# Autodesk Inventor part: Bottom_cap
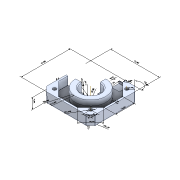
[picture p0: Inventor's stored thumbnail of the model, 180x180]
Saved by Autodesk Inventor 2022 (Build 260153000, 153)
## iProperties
Created: 2020-10
Part Number: Bottom_cap
Material: Generico
Document SubType Name: Modeling
Designer: admin
Density: 1 g/cm^3
Appearance: Default
Sending System: SolidWorks 2020
Last Author: Simon
Last Saved: 2020-10-31
Author: admin
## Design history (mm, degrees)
node "Annotazioni"
  node "Quota lineare 2" dims "d5" = 42 (derived), "d80" = 9.49768 (derived)
  node "Quota lineare 3" dims "d8" = 42 (derived), "d80" = 9.49768 (derived)
  node "Quota lineare 4" dims "d11" = 16.07149 (derived), "d80" = 9.49768 (derived)
  node "Quota lineare 5" dims "d14" = 16.07149 (derived), "d80" = 9.49768 (derived)
  node "Quota radiale 1" dims "d16" = 13 (derived), "d80" = 9.49768 (derived)
  node "Quota radiale 2" dims "d18" = 8 (derived), "d80" = 9.49768 (derived)
  node "Quota lineare 6" dims "d21" = 5.5 (derived), "d80" = 9.49768 (derived)
  node "Quota lineare 7" dims "d24" = 5.5 (derived), "d80" = 9.49768 (derived)
  node "Quota diametro 1" dims "d26" = 3 (derived), "d80" = 9.49768 (derived)
  node "Quota lineare 8" dims "d29" = 1.5 (derived), "d80" = 9.49768 (derived)
  node "Quota lineare 10" dims "d35" = 9 (derived), "d80" = 9.49768 (derived)
  node "Quota lineare 11" dims "d38" = 2 (derived), "d80" = 9.49768 (derived)
  node "Quota diametro 2" dims "d40" = 12 (derived), "d80" = 9.49768 (derived)
  node "Quota diametro 3" dims "d42" = 9 (derived), "d80" = 9.49768 (derived)
  node "Quota lineare 12" dims "d45" = 3.99939 (derived), "d80" = 9.49768 (derived)
  node "Quota lineare 13" dims "d48" = 1 (derived), "d80" = 9.49768 (derived)
  node "Quota lineare 14" dims "d51" = 0.62772 (derived), "d80" = 9.49768 (derived)
  node "Quota lineare 15" dims "d60" = 2.5 (derived), "d80" = 9.49768 (derived)
  node "Quota lineare 16" dims "d66" = 1.5 (derived), "d80" = 9.49768 (derived)
  node "Quota lineare 17" dims "d69" = 4.94975 (derived), "d80" = 9.49768 (derived)
  node "Quota angolare 1" dims "d72" = 135 deg (derived), "d80" = 9.49768 (derived)
  node "Quota lineare 18" dims "d75" = 7.24854 (derived), "d80" = 9.49768 (derived)
  node "Quota radiale 3" dims "d77" = 3 (derived), "d80" = 9.49768 (derived)
  node "Quota diametro 4" dims "d79" = 6.19654 (derived), "d80" = 9.49768 (derived)
  node "Quota lineare 19" dims "d80" = 9.49768 (derived), "d82" = 2 (derived)
  node "Quota diametro 5" dims "d80" = 9.49768 (derived), "d84" = 10 (derived)
fillet "Fillet7"
node "Asse di lavoro1"
node "Asse di lavoro2"
feature "Filettatura1" dims "d52" = 15, "d53" = 0
feature "Filettatura2" dims "d54" = 15, "d55" = 0
feature "Filettatura3" dims "d56" = 15, "d57" = 0
node "Asse di lavoro3"
node "Solido1"
other parameters: "d12" = 0 (derived), "d15" = 14.61797 (derived), "d17" = 12.87277 (derived), "d19" = 8.92075 (derived), "d20" = 0.83591 (derived), "d22" = 0.62622 (derived), "d23" = 0.15516 (derived), "d25" = 18.64797 (derived), "d27" = 5.0804 (derived), "d28" = 5.20268 (derived), "d3" = 2.98413 (derived), "d33" = 7.81774 (derived), "d34" = 0.54901 (derived), "d36" = 5.17941 (derived), "d37" = 0.83579 (derived), "d39" = 60.14052 (derived), "d4" = 5.26559 (derived), "d41" = 52.3533 (derived), "d43" = 6.69281 (derived), "d44" = 4.1142 (derived), "d46" = 6.86803 (derived), "d47" = 7.37418 (derived), "d49" = 3.74854 (derived), "d50" = 5.23199 (derived), "d58" = 5.33035 (derived), "d59" = 9.57753 (derived), "d6" = 7.23224 (derived), "d64" = 5.28138 (derived), "d65" = 0.82304 (derived), "d67" = 0.88876 (derived), "d68" = 5.42221 (derived), "d7" = 5.66851 (derived), "d70" = 3.0013 (derived), "d71" = 7.06781 (derived), "d73" = 5.05621 (derived), "d74" = 4.53036 (derived), "d76" = 43.67799 (derived), "d78" = 4.87289 (derived), "d81" = 7.67288 (derived), "d83" = 58.71687 (derived), "d9" = 0 (derived)
